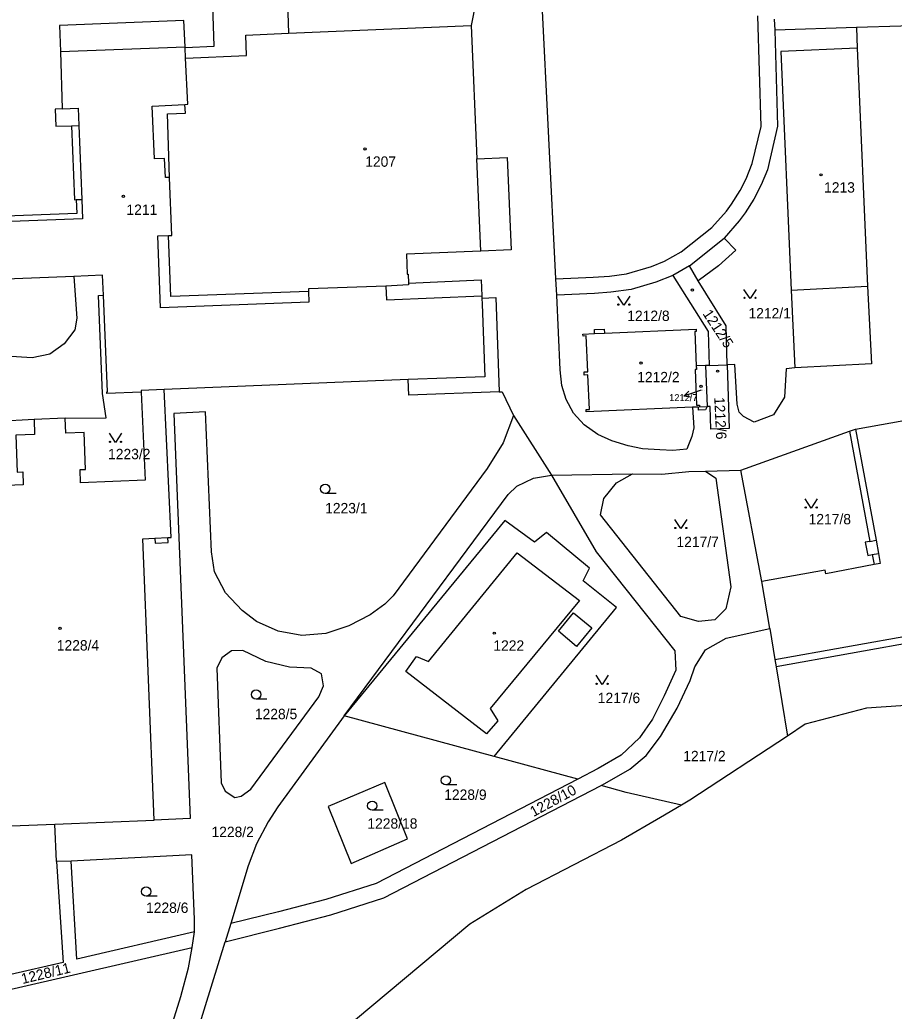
# Model space of a CAD drawing. Extents: x -737240 to -735272, y -1119606 to -1117878.
# Drawn here: x -736364.4 to -736220.9, y -1119244 to -1119081.3 of the extents above; entities that cross this region are included whole.
import ezdxf

# ---------------------------------------------------------------- set-up
doc = ezdxf.new("R2010")
doc.units = 0
for name, color, linetype in [('Level 1', 7, 'Continuous'), ('Level 16', 7, 'Continuous'), ('Level 18', 7, 'Continuous'), ('Level 19', 7, 'Continuous'), ('Level 25', 7, 'Continuous'), ('Level 4', 7, 'Continuous')]:
    doc.layers.add(name, color=color, linetype=linetype)

msp = doc.modelspace()

# ---------------------------------------------------------------- linework, layer by layer
at = {"layer": 'Level 1'}
for p, q in [((-736276.42, -1119123.84), (-736282.06, -1119011.1)), ((-736320.29, -1119083.54), (-736290.33, -1119082.25)), ((-736290.33, -1119082.25), (-736289.41, -1119104.15)), ((-736227.13, -1119082.62), (-736240.49, -1119083.04)), ((-736227.13, -1119082.62), (-736226.98, -1119086)), ((-736357.75, -1119086.54), (-736357.45, -1119095.94)), ((-736337.29, -1119085.85), (-736337.29, -1119085.75)), ((-736337.2, -1119087.63), (-736337.29, -1119085.85)), ((-736226.98, -1119086), (-736225.28, -1119125.06)), ((-736254.52, -1119121.73), (-736257.26, -1119123.28)), ((-736253.08, -1119124.15), (-736254.52, -1119121.73)), ((-736355.55, -1119123.46), (-736391.51, -1119124.94)), ((-736276.3, -1119126.5), (-736276.42, -1119123.84)), ((-736237.82, -1119125.7), (-736237.22, -1119138.43)), ((-736288.58, -1119126.62), (-736288.57, -1119127.01)), ((-736251.91, -1119138.08), (-736253.42, -1119138.14)), ((-736251.28, -1119138.06), (-736251.91, -1119138.08)), ((-736251.91, -1119138.08), (-736251.62, -1119144.82)), ((-736251.28, -1119138.06), (-736248.31, -1119137.95)), ((-736300.65, -1119140.37), (-736340.69, -1119142.01)), ((-736356.96, -1119146.73), (-736362.06, -1119146.92)), ((-736283.38, -1119146.28), (-736277.17, -1119156.05)), ((-736227.27, -1119148.5), (-736214.17, -1119146.2)), ((-736246.1, -1119155.25), (-736228.26, -1119148.85)), ((-736228.26, -1119148.85), (-736227.27, -1119148.5)), ((-736228.26, -1119148.85), (-736224.94, -1119166.93)), ((-736251.88, -1119155.4), (-736246.1, -1119155.25)), ((-736242.64, -1119173.5), (-736246.1, -1119155.25)), ((-736277.17, -1119156.05), (-736263.85, -1119155.87)), ((-736224.53, -1119169.11), (-736224.18, -1119170.75)), ((-736241.35, -1119181.24), (-736242.64, -1119173.5)), ((-736241.35, -1119181.24), (-736240.51, -1119186.31)), ((-736240.51, -1119186.31), (-736240.31, -1119187.52)), ((-736240.31, -1119187.52), (-736238.42, -1119198.88)), ((-736286.57, -1119202.23), (-736311.18, -1119195.59)), ((-736272.85, -1119205.97), (-736286.57, -1119202.23)), ((-736358.68, -1119213.35), (-736342.35, -1119212.67)), ((-736358.37, -1119219.5), (-736358.68, -1119213.35)), ((-736356, -1119219.43), (-736358.37, -1119219.5)), ((-736329.75, -1119229.66), (-736330.73, -1119232.67)), ((-736336.1, -1119233.59), (-736335.71, -1119231.04))]:
    msp.add_line(p, q, dxfattribs=at)
for points in [[(-736364.42, -1119002.59), (-736364.27, -1119006.54), (-736290.95, -1119003.74), (-736290.94, -1119004.04), (-736292.04, -1119004.06), (-736288.93, -1119071.15), (-736288.87, -1119074.72), (-736290.33, -1119082.25)], [(-736337.29, -1119085.85), (-736332.5, -1119085.64), (-736332.75, -1119079.05), (-736320.46, -1119078.56), (-736320.29, -1119083.54)], [(-736337.29, -1119085.75), (-736337.46, -1119081.45), (-736357.91, -1119082.29), (-736357.75, -1119086.54)], [(-736276.42, -1119123.84), (-736270.29, -1119123.58), (-736267.61, -1119123.39), (-736264.83, -1119123.02), (-736260.77, -1119121.84), (-736258.59, -1119120.94), (-736255.85, -1119119.39), (-736250.83, -1119115.4), (-736248.42, -1119112.75), (-736247.64, -1119111.61), (-736246.22, -1119109.36), (-736245.22, -1119107.41), (-736244.21, -1119104.93), (-736242.75, -1119098.85), (-736243.28, -1119080.7)], [(-736195.52, -1119081.98), (-736201.18, -1119082.18), (-736201.13, -1119083.73), (-736205.18, -1119083.91), (-736205.3, -1119081.94), (-736227.13, -1119082.62)], [(-736240.49, -1119083.04), (-736240.08, -1119098.77), (-736241.73, -1119105.94), (-736242.74, -1119108.42), (-736243.96, -1119110.79), (-736245.38, -1119113.04), (-736246.35, -1119114.32), (-736248.82, -1119117.15)], [(-736226.98, -1119086), (-736239.54, -1119086.56), (-736237.82, -1119125.7)], [(-736337.31, -1119095.21), (-736336.83, -1119095.19), (-736337.2, -1119087.63)], [(-736339.82, -1119107.19), (-736340.19, -1119096.79), (-736337.24, -1119096.65), (-736337.31, -1119095.21)], [(-736357.45, -1119095.94), (-736358.58, -1119096.01), (-736358.51, -1119098.79), (-736355.9, -1119098.72)], [(-736355.9, -1119098.72), (-736355.42, -1119110.86), (-736355.14, -1119110.85)], [(-736289.41, -1119104.15), (-736284.42, -1119103.94), (-736283.78, -1119119.1), (-736288.75, -1119119.29)], [(-736355.55, -1119123.46), (-736355.07, -1119130.3), (-736355.37, -1119132.23), (-736357.1, -1119134.49), (-736359.5, -1119136.23), (-736362.35, -1119136.79), (-736396.16, -1119134.69), (-736400.97, -1119133.77), (-736405.69, -1119132), (-736409.9, -1119129.38), (-736413.65, -1119126.02), (-736417.3, -1119121.3), (-736417.95, -1119119.46), (-736416.79, -1119117.82), (-736417.93, -1119112.07), (-736418.13, -1119107.97)], [(-736339.99, -1119116.73), (-736339.48, -1119116.71), (-736339.82, -1119107.19)], [(-736355.14, -1119110.85), (-736355.05, -1119113.14), (-736371.13, -1119113.73), (-736371.27, -1119110.85), (-736372.47, -1119110.9), (-736372.5, -1119110.01), (-736408.9, -1119111.35), (-736408.79, -1119114.24), (-736413.26, -1119114.42), (-736413.13, -1119116.28)], [(-736317.03, -1119125.91), (-736339.64, -1119126.75), (-736339.99, -1119116.73)], [(-736248.82, -1119117.15), (-736246.88, -1119119.13), (-736249.77, -1119121.72), (-736253.08, -1119124.15)], [(-736288.75, -1119119.29), (-736300.94, -1119119.82), (-736300.85, -1119123.08), (-736300.68, -1119123.07), (-736300.63, -1119124.54)], [(-736350.67, -1119126.54), (-736350.81, -1119123.27), (-736355.55, -1119123.46)], [(-736300.63, -1119124.54), (-736288.7, -1119124.02), (-736288.58, -1119126.62)], [(-736257.26, -1119123.28), (-736260.03, -1119124.4), (-736264.09, -1119125.58), (-736267.42, -1119126.04), (-736270.1, -1119126.23), (-736276.3, -1119126.5)], [(-736257.26, -1119123.28), (-736251.46, -1119132.47), (-736251.28, -1119138.06)], [(-736248.31, -1119137.95), (-736248.5, -1119131.58), (-736251.82, -1119126.21), (-736253.08, -1119124.15)], [(-736304.33, -1119125.03), (-736317.05, -1119125.5), (-736317.03, -1119125.91)], [(-736300.63, -1119124.54), (-736300.62, -1119124.85), (-736304.33, -1119125.03)], [(-736225.28, -1119125.06), (-736224.63, -1119137.81), (-736237.22, -1119138.43)], [(-736356.96, -1119146.73), (-736350.24, -1119146.66), (-736350.85, -1119142.67), (-736351.51, -1119126.58), (-736350.67, -1119126.54)], [(-736344.48, -1119142.42), (-736350.13, -1119142.65), (-736350.14, -1119142.39), (-736350.01, -1119142.38), (-736350.67, -1119126.54)], [(-736288.57, -1119127.01), (-736286.3, -1119126.93), (-736285.72, -1119142.4)], [(-736254, -1119144.93), (-736253.79, -1119148.31), (-736254.1, -1119149.75), (-736254.66, -1119151.11), (-736254.95, -1119151.79), (-736257.27, -1119152), (-736259.35, -1119151.9), (-736262.21, -1119151.77), (-736264.56, -1119151.23), (-736267.28, -1119150.43), (-736269.53, -1119149.37), (-736271.79, -1119147.79), (-736273.57, -1119145.88), (-736274.74, -1119143.65), (-736275.46, -1119141.34), (-736275.71, -1119138.8), (-736276.3, -1119126.5)], [(-736270.08, -1119132.82), (-736270.11, -1119132.15), (-736268.51, -1119132.08), (-736268.48, -1119132.75)], [(-736268.48, -1119132.75), (-736253.43, -1119132.1), (-736253.42, -1119132.49), (-736253.66, -1119132.51), (-736253.42, -1119138.14)], [(-736254, -1119144.93), (-736271.44, -1119145.68), (-736271.45, -1119145.31), (-736270.94, -1119145.29), (-736271.18, -1119139.61), (-736271.77, -1119139.63), (-736271.79, -1119139.11), (-736271.21, -1119139.09), (-736271.46, -1119133.21), (-736271.98, -1119133.24), (-736271.99, -1119132.9), (-736270.08, -1119132.82)], [(-736253.42, -1119138.14), (-736253.41, -1119138.39), (-736253.35, -1119138.39), (-736253.35, -1119138.71), (-736253.59, -1119138.72), (-736253.34, -1119144.58), (-736252.89, -1119144.56), (-736252.89, -1119144.88), (-736251.62, -1119144.82)], [(-736248.31, -1119137.95), (-736248, -1119148.42), (-736251, -1119148.53), (-736251.1, -1119144.82), (-736251.62, -1119144.82)], [(-736237.22, -1119138.43), (-736238.62, -1119138.62), (-736238.9, -1119143.25), (-736240.75, -1119146.15), (-736243.89, -1119147.39), (-736245.66, -1119146.43), (-736246.36, -1119145.73), (-736246.7, -1119144.42), (-736247.08, -1119137.91), (-736248.31, -1119137.95)], [(-736362.06, -1119146.92), (-736368.05, -1119147.26), (-736374.29, -1119141.38), (-736393.2, -1119140.28), (-736395.88, -1119141.44), (-736398.9, -1119143.98), (-736401.09, -1119147.35), (-736401.8, -1119150.24), (-736405.14, -1119180.46)], [(-736285.72, -1119142.4), (-736300.55, -1119142.96), (-736300.65, -1119140.37)], [(-736344.48, -1119142.42), (-736343.82, -1119156.91), (-736354.45, -1119157.35), (-736354.52, -1119155.15), (-736353.65, -1119155.12), (-736353.83, -1119149.05), (-736356.87, -1119149.18), (-736356.96, -1119146.73)], [(-736340.69, -1119142.01), (-736344.5, -1119142.16), (-736344.48, -1119142.42)], [(-736340.1, -1119166.32), (-736339.58, -1119166.29), (-736340.69, -1119142.01)], [(-736285.72, -1119142.4), (-736285.24, -1119142.4), (-736283.38, -1119146.28)], [(-736251.62, -1119144.82), (-736251.91, -1119145.37), (-736253.02, -1119145.41), (-736253.04, -1119144.89), (-736254, -1119144.93)], [(-736362.06, -1119146.92), (-736361.97, -1119149.37), (-736365.04, -1119149.51), (-736364.81, -1119155.55), (-736363.93, -1119155.51), (-736363.85, -1119157.64), (-736373.64, -1119158.04), (-736371.44, -1119213.85), (-736358.68, -1119213.35)], [(-736283.38, -1119146.28), (-736285.11, -1119150.79), (-736287.71, -1119155), (-736303.12, -1119175.9), (-736304.49, -1119177.22), (-736306.92, -1119179.02), (-736310.39, -1119180.81), (-736314.2, -1119182.05), (-736318.14, -1119182.41), (-736321.99, -1119181.7), (-736325.58, -1119180.08), (-736327.9, -1119178.26), (-736330.64, -1119175.39), (-736332.45, -1119171.94), (-736332.93, -1119168.63), (-736333.95, -1119145.7), (-736339.13, -1119145.94), (-736336.43, -1119212.44), (-736342.35, -1119212.67)], [(-736251.88, -1119155.4), (-736250.16, -1119156.56), (-736247.71, -1119174.41), (-736248.54, -1119178.02), (-736250.34, -1119179.79), (-736253.04, -1119180.08), (-736255.91, -1119179.27), (-736269.12, -1119162.56), (-736268.59, -1119159.91), (-736266.48, -1119157.32), (-736263.85, -1119155.87)], [(-736263.85, -1119155.87), (-736259.07, -1119155.89), (-736254.62, -1119155.48), (-736251.88, -1119155.4)], [(-736311.18, -1119195.59), (-736284.25, -1119159.24), (-736282.85, -1119157.88), (-736280.13, -1119156.58), (-736277.17, -1119156.05)], [(-736277.17, -1119156.05), (-736269.84, -1119168.63), (-736256.91, -1119184.91), (-736256.75, -1119188.06), (-736258.69, -1119192.27), (-736260.6, -1119196.11), (-736262.7, -1119199.19), (-736265.73, -1119202.05), (-736269.49, -1119204.23), (-736272.85, -1119205.97)], [(-736286.57, -1119202.23), (-736266.5, -1119177.8), (-736271.94, -1119173.4), (-736270.93, -1119171.34), (-736277.99, -1119165.46), (-736279.97, -1119167.06), (-736284.8, -1119163.52), (-736311.18, -1119195.59)], [(-736342.35, -1119212.67), (-736344.22, -1119166.5), (-736342.23, -1119166.41)], [(-736342.23, -1119166.41), (-736342.19, -1119167.21), (-736340.07, -1119167.11), (-736340.1, -1119166.32)], [(-736224.94, -1119166.93), (-736225.67, -1119167.06), (-736225.27, -1119169.24), (-736224.53, -1119169.11)], [(-736224.18, -1119170.75), (-736232.16, -1119172.24), (-736232.26, -1119171.68), (-736242.64, -1119173.5)], [(-736191.71, -1119177.58), (-736191.51, -1119178.76), (-736240.31, -1119187.52)], [(-736358.37, -1119219.5), (-736357.31, -1119236.05), (-736365.86, -1119238), (-736370.84, -1119239.02), (-736373.1, -1119238.97), (-736376.8, -1119238.39), (-736380.64, -1119237.35), (-736384.25, -1119235.72), (-736387.56, -1119233.23), (-736389.67, -1119231.05), (-736392.43, -1119226.85), (-736394.65, -1119221.82), (-736396.17, -1119217.14), (-736405.14, -1119180.46)], [(-736269.02, -1119207.01), (-736268.39, -1119206.69), (-736264.3, -1119204.35), (-736261.63, -1119202.09), (-736259.26, -1119198.94), (-736256.52, -1119194.32), (-736254.4, -1119189.77), (-736253.65, -1119187.53), (-736251.91, -1119184.76), (-736248.49, -1119182.84), (-736241.35, -1119181.24)], [(-736320.17, -1119187.58), (-736324.05, -1119186.66), (-736327.79, -1119184.85), (-736329.65, -1119184.89), (-736331.26, -1119186.04), (-736332.09, -1119187.77), (-736331.36, -1119206.55), (-736330.7, -1119207.91), (-736329.12, -1119208.97), (-736328.1, -1119208.78), (-736326.5, -1119207.6), (-736315.34, -1119192.44), (-736314.59, -1119190.66), (-736314.91, -1119188.68), (-736316.59, -1119187.75), (-736320.17, -1119187.58)], [(-736406.02, -1119188.26), (-736413.99, -1119262), (-736414, -1119265), (-736413.66, -1119268.91), (-736413.29, -1119270.8), (-736411.87, -1119274.54), (-736409.93, -1119278.12), (-736404.25, -1119283.76), (-736400.66, -1119285.68), (-736396.86, -1119286.78), (-736392.86, -1119287.18), (-736368.91, -1119286.32), (-736366.01, -1119286.05), (-736363.13, -1119285.22), (-736359.5, -1119283.68), (-736356.12, -1119281.69), (-736352.94, -1119279.25), (-736350.32, -1119276.22), (-736348.2, -1119272.9), (-736346.64, -1119269.31), (-736338, -1119241.65), (-736336.72, -1119236.91), (-736336.1, -1119233.59)], [(-736406.02, -1119188.26), (-736405.36, -1119189.52), (-736398.47, -1119217.84), (-736396.91, -1119222.59), (-736394.49, -1119227.98), (-736391.55, -1119232.46), (-736389.22, -1119234.96), (-736385.41, -1119237.79), (-736381.33, -1119239.64), (-736377.22, -1119240.73), (-736373.18, -1119241.36), (-736370.46, -1119241.35), (-736365.31, -1119240.32), (-736336.1, -1119233.59)], [(-736186.32, -1119192.52), (-736187.27, -1119192.66), (-736201.31, -1119192.65), (-736225.46, -1119194.3), (-736235.51, -1119196.96), (-736238.42, -1119198.88)], [(-736311.18, -1119195.59), (-736322.06, -1119210.53), (-736323.63, -1119212.96), (-736325.55, -1119216.57), (-736326.92, -1119220.21), (-736329.75, -1119229.66)], [(-736238.42, -1119198.88), (-736254.43, -1119209.41), (-736255.81, -1119210.22)], [(-736330.73, -1119232.67), (-736321.79, -1119230.44), (-736313.36, -1119228.22), (-736304.66, -1119225.42), (-736269.02, -1119207.01)], [(-736272.85, -1119205.97), (-736305.91, -1119223.07), (-736314.16, -1119225.73), (-736321.93, -1119227.72), (-736329.75, -1119229.66)], [(-736313.82, -1119210.45), (-736310.05, -1119219.79), (-736300.77, -1119215.75), (-736304.52, -1119206.53), (-736313.82, -1119210.45)], [(-736255.81, -1119210.22), (-736264.9, -1119208.13), (-736269.02, -1119207.01)], [(-736255.81, -1119210.22), (-736259.28, -1119212.27), (-736265.67, -1119215.95), (-736281.3, -1119224.06), (-736290.58, -1119229.79), (-736309.29, -1119245.48), (-736321.63, -1119256.65), (-736324.44, -1119259.95), (-736330.29, -1119268.45), (-736331.86, -1119271.65), (-736337.39, -1119288.32), (-736338.43, -1119295.05), (-736330.86, -1119325.76)], [(-736335.71, -1119231.04), (-736335.71, -1119229), (-736336.16, -1119218.4), (-736356, -1119219.43)], [(-736335.71, -1119231.04), (-736355.04, -1119235.49), (-736356, -1119219.43)], [(-736366.57, -1119290.55), (-736363.63, -1119289.96), (-736359.83, -1119288.6), (-736355.36, -1119286.51), (-736351.29, -1119283.55), (-736347.72, -1119280.02), (-736344.91, -1119275.94), (-736342.71, -1119271.47), (-736330.73, -1119232.67)]]:
    msp.add_lwpolyline(points, dxfattribs=at)
at = {"layer": 'Level 16'}
msp.add_line((-736252.59, -1119142.13), (-736255.429, -1119143.1), dxfattribs=at)
msp.add_lwpolyline([(-736254.321, -1119143.25), (-736255.429, -1119143.1), (-736254.644, -1119142.304)], dxfattribs=at)
at = {"layer": 'Level 25'}
for p, q in [((-736312.498, -1119159.07), (-736314.28, -1119159.07)), ((-736323.848, -1119192.83), (-736325.63, -1119192.83)), ((-736292.698, -1119206.92), (-736294.48, -1119206.92)), ((-736304.788, -1119211.08), (-736306.57, -1119211.08)), ((-736341.888, -1119225.17), (-736343.67, -1119225.17))]:
    msp.add_line(p, q, dxfattribs=at)
for points in [[(-736243.58, -1119125.57), (-736244.58, -1119127.07), (-736245.58, -1119125.57)], [(-736264.28, -1119126.67), (-736265.28, -1119128.17), (-736266.28, -1119126.67)], [(-736347.7, -1119149.19), (-736348.7, -1119150.69), (-736349.7, -1119149.19)], [(-736233.54, -1119159.97), (-736234.54, -1119161.47), (-736235.54, -1119159.97)], [(-736254.93, -1119163.34), (-736255.93, -1119164.84), (-736256.93, -1119163.34)], [(-736267.85, -1119188.92), (-736268.85, -1119190.42), (-736269.85, -1119188.92)]]:
    msp.add_lwpolyline(points, dxfattribs=at)
for centre in [(-736245.48, -1119126.97), (-736243.68, -1119126.97), (-736266.18, -1119128.07), (-736264.38, -1119128.07), (-736349.6, -1119150.59), (-736347.8, -1119150.59), (-736235.44, -1119161.37), (-736233.64, -1119161.37), (-736256.83, -1119164.74), (-736255.03, -1119164.74), (-736269.75, -1119190.32), (-736267.95, -1119190.32)]:
    msp.add_circle(centre, 0.1, dxfattribs=at)
for centre, major_axis, ratio in [((-736307.75, -1119102.53), (0.18, 0), 0.9848078), ((-736232.92, -1119106.78), (0.18, 0), 0.9848078), ((-736347.4, -1119110.31), (0.18, 0), 0.9848078), ((-736254.04, -1119125.68), (0.18, 0), 0.9848078), ((-736262.46, -1119137.67), (0.18, 0), 0.9848078), ((-736249.9, -1119138.99), (0.18, 0), 0.9848078), ((-736252.62, -1119141.49), (0.18, 0), 0.9848078), ((-736314.28, -1119158.314), (0.764, 0), 0.9894236), ((-736357.8, -1119181.21), (0.18, 0), 0.9848078), ((-736286.55, -1119182.01), (0.18, 0), 0.9848078), ((-736325.63, -1119192.074), (0.764, 0), 0.9894236), ((-736294.48, -1119206.164), (0.764, 0), 0.9894236), ((-736306.57, -1119210.324), (0.764, 0), 0.9894236), ((-736343.67, -1119224.414), (0.764, 0), 0.9894236)]:
    msp.add_ellipse(centre, major_axis=major_axis, ratio=ratio, dxfattribs=at)
at = {"layer": 'Level 4'}
for p, q in [((-736240.6, -1119081.22), (-736240.49, -1119083.04)), ((-736357.75, -1119086.54), (-736337.29, -1119085.75)), ((-736355.9, -1119098.72), (-736354.72, -1119098.69)), ((-736354.72, -1119098.69), (-736354.24, -1119110.81)), ((-736288.75, -1119119.29), (-736289.41, -1119104.15)), ((-736355.14, -1119110.85), (-736354.24, -1119110.81)), ((-736254.52, -1119121.73), (-736248.82, -1119117.15)), ((-736237.82, -1119125.7), (-736225.28, -1119125.06)), ((-736270.08, -1119132.82), (-736268.48, -1119132.75)), ((-736227.27, -1119148.5), (-736223.9, -1119166.73)), ((-736342.23, -1119166.41), (-736340.1, -1119166.32)), ((-736224.94, -1119166.93), (-736223.9, -1119166.73)), ((-736223.9, -1119166.73), (-736223.5, -1119168.92)), ((-736224.53, -1119169.11), (-736223.5, -1119168.92)), ((-736240.51, -1119186.31), (-736191.71, -1119177.58))]:
    msp.add_line(p, q, dxfattribs=at)
for points in [[(-736337.2, -1119087.63), (-736327.18, -1119087.18), (-736327.32, -1119083.83), (-736320.29, -1119083.54)], [(-736339.82, -1119107.19), (-736340.51, -1119107.21), (-736340.66, -1119104.08), (-736342.28, -1119104.16), (-736342.71, -1119095.48), (-736337.31, -1119095.21)], [(-736357.45, -1119095.94), (-736354.83, -1119095.86), (-736354.72, -1119098.69)], [(-736354.24, -1119110.81), (-736354.11, -1119114), (-736373.23, -1119114.71), (-736373.37, -1119110.92), (-736407.97, -1119112.21), (-736407.9, -1119114.21), (-736407.82, -1119116.27)], [(-736317.03, -1119125.91), (-736316.97, -1119127.7), (-736341.34, -1119128.63), (-736341.76, -1119116.79), (-736339.99, -1119116.73)], [(-736304.33, -1119125.03), (-736304.25, -1119127.27), (-736288.58, -1119126.62)], [(-736288.57, -1119127.01), (-736288.53, -1119128.02), (-736288.12, -1119139.94), (-736300.65, -1119140.37)], [(-736299.31, -1119185.83), (-736297.36, -1119186.63), (-736282.8, -1119168.81), (-736272.57, -1119176.65), (-736287.21, -1119194.39), (-736285.97, -1119196.39), (-736287.82, -1119198.52), (-736301.07, -1119188.29), (-736299.31, -1119185.83)], [(-736223.5, -1119168.92), (-736223.2, -1119170.57), (-736224.18, -1119170.75)], [(-736270.54, -1119181.12), (-736273.03, -1119184.17), (-736276.03, -1119181.68), (-736273.56, -1119178.66), (-736270.54, -1119181.12)]]:
    msp.add_lwpolyline(points, dxfattribs=at)

# ---------------------------------------------------------------- texts
at = {"layer": 'Level 16'}
msp.add_text('1212/7', height=1.14, dxfattribs=at).set_placement((-736257.85, -1119143.91))
at = {"layer": 'Level 18'}
for s, p in [('1212/8', (-736264.72, -1119130.76)), ('1212/1', (-736244.83, -1119130.34)), ('1223/2', (-736349.92, -1119153.45)), ('1223/1', (-736314.3, -1119162.33)), ('1217/8', (-736234.96, -1119164.14)), ('1217/7', (-736256.65, -1119167.87)), ('1217/6', (-736269.56, -1119193.48)), ('1228/5', (-736325.83, -1119196.12)), ('1217/2', (-736255.53, -1119203.02)), ('1228/9', (-736294.76, -1119209.36)), ('1228/18', (-736307.37, -1119214.09)), ('1228/2', (-736332.95, -1119215.47)), ('1228/6', (-736343.69, -1119227.92))]:
    msp.add_text(s, height=1.7, dxfattribs=at).set_placement(p)
for s, rotation, p in [('1228/10', 28.57122, (-736280.107, -1119212.197)), ('1228/11', 13.4748, (-736363.957, -1119239.597))]:
    msp.add_text(s, height=1.7, rotation=rotation, dxfattribs=at).set_placement(p)
at = {"layer": 'Level 19'}
for s, height, p in [('1207', 1.7, (-736307.72, -1119105.45)), ('1213', 1.7, (-736232.425, -1119109.69)), ('1211', 1.7, (-736346.905, -1119113.35)), ('1212/2', 1.7, (-736263.095, -1119140.82)), ('1212/7', 0.1, (-736252.415, -1119142.13)), ('1228/4', 1.7, (-736358.335, -1119184.85)), ('1222', 1.7, (-736286.695, -1119184.88))]:
    msp.add_text(s, height=height, dxfattribs=at).set_placement(p)
for s, rotation, p in [('1212/5', 303.3, (-736252.42, -1119129.57)), ('1212/6', 272.7, (-736250.45, -1119143.3))]:
    msp.add_text(s, height=1.7, rotation=rotation, dxfattribs=at).set_placement(p)

doc.saveas('drawing.dxf')
